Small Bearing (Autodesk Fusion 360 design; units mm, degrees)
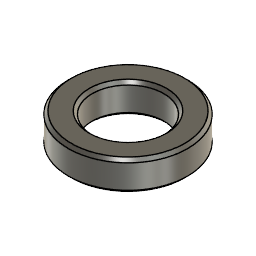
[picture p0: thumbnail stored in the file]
part number: 2025-12-16-11-00-29-093
sketch "Sketch1" plane through (0, 0, 0) normal (0, 0, 1) x axis (1, 0, 0)
  circle C1 centre (0, 0) radius 5
  circle C2 centre (0, 0) radius 3
  point P1 (0, 0)
  point P2 (0, 0)
  point P3 (0, 0)
  coincident P1 P2
  coincident P1 P3
  dimension "d1" diameter C1 = 10
  dimension "d2" diameter C2 = 6
extrude "Extrude1" new body sketch "Sketch1" along normal blind 2.5
chamfer "Chamfer1" distance 0.25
